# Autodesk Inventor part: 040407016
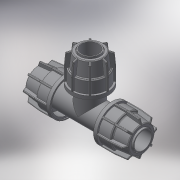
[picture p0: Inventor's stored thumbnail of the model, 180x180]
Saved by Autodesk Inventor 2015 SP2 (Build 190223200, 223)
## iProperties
Created: 2017-08
Part Number: 040407016
Material: Generic
Description: PLASSON IRRIFIT TEE 16-16-16
Document SubType Name: Modeling
Designer: KIM
Density: 1 g/cm^3
Appearance: Default
Author: KIM
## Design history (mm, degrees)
derived "040407.ipt"
feature "Solid1::040407.ipt"
tag "TaggingFeature1"
body "Solid1"
other parameters: "d5" = 28.8, "d6" = 14.4, "d10" = 34, "d22" = 22.4, "d24" = 3.2, "d25" = 30.6, "d26" = 27.2, "d31" = 0.8, "d49" = 1.7, "d50" = 0, "d58" = 0.48, "d61" = 360 deg, "d77" = 16, "d78" = 6 deg, "d80" = 17.6, "d81" = 49, "d82" = 2.4, "d84" = 5 deg, "d85" = 70 deg, "d86" = 32.3, "d87" = 0.8, "d88" = 0, "d89" = 28.9, "d90" = 8, "d91" = 0, "d93" = 180 deg, "d96" = 0, "d98" = 0, "d_" = 16, "E_" = 34, "H_" = 98, "l_" = 16
